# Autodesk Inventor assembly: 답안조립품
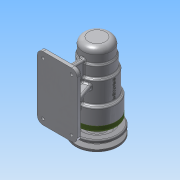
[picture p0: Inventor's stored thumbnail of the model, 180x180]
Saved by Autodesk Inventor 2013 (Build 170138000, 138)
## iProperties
Created: 2016-06
Part Number: 답안조립품
Document SubType Name: Assembly
Designer: Administrator
Author: Administrator
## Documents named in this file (12)
- C:\Users\Administrator\Desktop\460608V1008\답안조립품.iam
- C:\Users\Administrator\Desktop\460608V1008\본체.ipt
- C:\Users\Administrator\Desktop\460608V1008\V벨트풀리.ipt
- C:\Users\Administrator\Desktop\460608V1008\멈춤나사 M3x8.ipt
- C:\Users\Administrator\Desktop\460608V1008\베어링 6004.ipt
- C:\Users\Administrator\Desktop\460608V1008\베어링 51202.ipt
- C:\Users\Administrator\Desktop\460608V1008\볼트 M4 x 12.ipt
- C:\Users\Administrator\Desktop\460608V1008\어댑터슬리브.ipt
- C:\Users\Administrator\Desktop\460608V1008\오일 실.ipt
- C:\Users\Administrator\Desktop\460608V1008\축.ipt
- C:\Users\Administrator\Desktop\460608V1008\커버.ipt
- C:\Users\Administrator\Desktop\460608V1008\키 5 x 5 x 16.ipt
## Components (5 placed, 2 different names)
1. V벨트풀리:1
2. ISO 4762 M4 x 12:1
3. ISO 4762 M4 x 12:2
4. ISO 4762 M4 x 12:3
5. ISO 4762 M4 x 12:4
